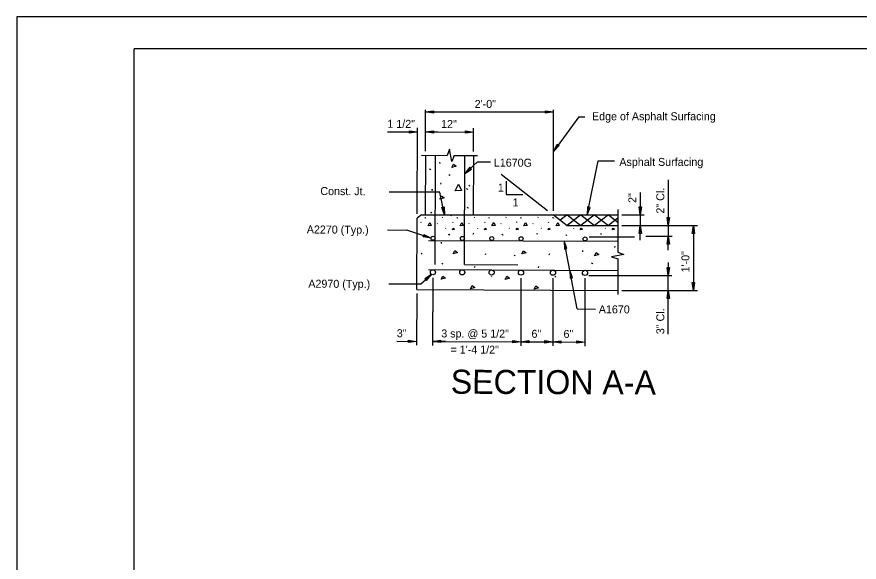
# Model space of a CAD drawing. Extents: x 2799.7 to 2896, y 515.2 to 573.9.
# Drawn here: x 2799.69 to 2834.77, y 551.18 to 573.89 of the extents above; entities that cross this region are included whole.
import ezdxf

# ---------------------------------------------------------------- set-up
doc = ezdxf.new("R2010")
doc.units = 0
for name, color, linetype in [('BR_AUTO DIMENSION', 7, 'Continuous'), ('BR_BORDER LINES', 7, 'Continuous'), ('BR_CONCRETE', 7, 'Continuous'), ('BR_DETAILS', 7, 'Continuous'), ('BR_REBAR', 7, 'Continuous'), ('BR_TABLE LINES', 7, 'Continuous'), ('BR_TEXT', 7, 'Continuous'), ('Level 31', 7, 'Continuous')]:
    doc.layers.add(name, color=color, linetype=linetype)

msp = doc.modelspace()

# ---------------------------------------------------------------- linework, layer by layer
at = {"layer": 'BR_AUTO DIMENSION'}
for p, q in [((2816.709, 568.294), (2816.709, 570.014)), ((2816.709, 569.93), (2822.042, 569.93)), ((2822.042, 565.808), (2822.042, 570.014)), ((2823.098, 569.724), (2822.042, 568.287)), ((2823.098, 569.724), (2823.349, 569.724)), ((2815.124, 569.104), (2816.38, 569.099)), ((2816.366, 565.69), (2816.38, 569.265)), ((2816.71, 568.294), (2816.714, 569.264)), ((2816.71, 568.294), (2816.714, 569.264)), ((2817.246, 569.095), (2816.713, 569.097)), ((2816.713, 569.097), (2818.713, 569.089)), ((2818.71, 568.286), (2818.714, 569.256)), ((2818.872, 567.855), (2818.354, 567.36)), ((2818.872, 567.855), (2819.425, 567.853)), ((2823.449, 565.641), (2823.908, 567.901)), ((2823.908, 567.901), (2824.59, 567.901)), ((2819.864, 567.336), (2821.798, 565.832)), ((2820.074, 567.05), (2820.074, 566.489)), ((2826.826, 567.108), (2826.826, 565.197)), ((2817.315, 566.584), (2815.196, 566.593)), ((2817.502, 565.641), (2817.315, 566.584)), ((2825.659, 566.578), (2825.659, 565.641)), ((2820.074, 566.489), (2820.772, 566.489)), ((2824.887, 565.641), (2825.826, 565.641)), ((2825.659, 565.641), (2825.659, 565.197)), ((2824.887, 565.197), (2825.826, 565.197)), ((2824.887, 565.197), (2828.037, 565.197)), ((2824.887, 565.197), (2826.992, 565.197)), ((2825.659, 564.595), (2825.659, 565.197)), ((2826.826, 565.197), (2826.826, 564.752)), ((2827.87, 565.197), (2827.87, 562.496)), ((2815.126, 565.016), (2815.941, 565.013)), ((2816.937, 564.671), (2815.941, 565.013)), ((2823.036, 561.725), (2822.484, 564.56)), ((2823.525, 564.725), (2825.421, 564.725)), ((2825.895, 564.752), (2826.992, 564.752)), ((2826.062, 564.752), (2826.992, 564.752)), ((2826.826, 564.176), (2826.826, 564.752)), ((2826.826, 564.219), (2826.826, 564.752)), ((2826.826, 563.654), (2826.826, 563.121)), ((2816.499, 562.757), (2816.968, 563.161)), ((2823.519, 563.121), (2826.968, 563.121)), ((2826.826, 562.496), (2826.826, 563.121)), ((2816.499, 562.757), (2815.188, 562.763)), ((2817.022, 563.029), (2817.01, 560.209)), ((2817.021, 562.981), (2817.01, 560.209)), ((2820.688, 563.014), (2820.677, 560.194)), ((2820.688, 563.014), (2820.677, 560.194)), ((2822.021, 563.008), (2822.01, 560.189)), ((2822.021, 563.008), (2822.01, 560.189)), ((2823.355, 563.003), (2823.343, 560.183)), ((2816.352, 562.365), (2816.343, 560.212)), ((2824.886, 562.496), (2828.037, 562.496)), ((2826.826, 560.676), (2826.826, 562.496)), ((2826.826, 561.963), (2826.826, 562.496)), ((2823.036, 561.725), (2823.788, 561.722)), ((2815.517, 560.382), (2816.344, 560.378)), ((2817.011, 560.376), (2820.677, 560.361)), ((2817.544, 560.374), (2817.011, 560.376)), ((2820.677, 560.361), (2822.011, 560.355)), ((2822.011, 560.355), (2823.344, 560.35))]:
    msp.add_line(p, q, dxfattribs=at)
for points in [[(2817.042, 569.88), (2816.709, 569.93), (2817.042, 569.98)], [(2821.709, 569.98), (2822.042, 569.93), (2821.709, 569.88)], [(2816.047, 569.15), (2816.38, 569.099), (2816.046, 569.05)], [(2817.046, 569.046), (2816.713, 569.097), (2817.047, 569.146)], [(2817.046, 569.046), (2816.713, 569.097), (2817.047, 569.146)], [(2818.38, 569.14), (2818.713, 569.089), (2818.379, 569.04)], [(2822.28, 568.526), (2822.042, 568.287), (2822.199, 568.585)], [(2818.561, 567.626), (2818.354, 567.36), (2818.63, 567.554)], [(2817.486, 565.978), (2817.502, 565.641), (2817.388, 565.958)], [(2823.466, 565.978), (2823.449, 565.641), (2823.564, 565.958)], [(2825.709, 565.975), (2825.659, 565.641), (2825.609, 565.975)], [(2826.876, 565.53), (2826.826, 565.197), (2826.776, 565.53)], [(2825.609, 564.863), (2825.659, 565.197), (2825.709, 564.863)], [(2825.609, 564.863), (2825.659, 565.197), (2825.709, 564.863)], [(2827.82, 564.863), (2827.87, 565.197), (2827.92, 564.863)], [(2816.643, 564.825), (2816.942, 564.67), (2816.61, 564.73)], [(2822.597, 564.242), (2822.484, 564.56), (2822.499, 564.223)], [(2826.776, 564.419), (2826.826, 564.752), (2826.876, 564.419)], [(2826.776, 564.419), (2826.826, 564.752), (2826.876, 564.419)], [(2826.876, 563.454), (2826.826, 563.121), (2826.776, 563.454)], [(2816.748, 562.906), (2816.968, 563.161), (2816.683, 562.982)], [(2822.835, 563.021), (2822.722, 563.339), (2822.736, 563.002)], [(2827.92, 562.83), (2827.87, 562.496), (2827.82, 562.83)], [(2826.776, 562.163), (2826.826, 562.496), (2826.876, 562.163)], [(2816.011, 560.43), (2816.344, 560.378), (2816.01, 560.33)], [(2817.344, 560.324), (2817.011, 560.376), (2817.344, 560.424)], [(2817.344, 560.324), (2817.011, 560.376), (2817.344, 560.424)], [(2820.344, 560.412), (2820.677, 560.361), (2820.344, 560.312)], [(2821.01, 560.309), (2820.677, 560.361), (2821.011, 560.409)], [(2821.677, 560.407), (2822.011, 560.355), (2821.677, 560.307)], [(2822.344, 560.304), (2822.011, 560.355), (2822.344, 560.404)], [(2823.011, 560.401), (2823.344, 560.35), (2823.01, 560.301)]]:
    msp.add_lwpolyline(points, close=True, dxfattribs=at)
at = {"layer": 'BR_BORDER LINES'}
for p in [(2894.359, 572.556), (2804.582, 516.556)]:
    msp.add_line(p, (2804.582, 572.556), dxfattribs=at)
at = {"layer": 'BR_CONCRETE'}
for p, q in [((2816.709, 568.127), (2816.699, 565.641)), ((2818.709, 568.119), (2818.699, 565.641)), ((2816.542, 565.641), (2816.365, 565.503)), ((2816.542, 565.641), (2822.042, 565.641)), ((2822.042, 565.641), (2822.614, 565.197)), ((2816.353, 562.532), (2816.365, 565.503)), ((2822.614, 565.197), (2824.72, 565.197)), ((2816.353, 562.532), (2824.72, 562.497))]:
    msp.add_line(p, q, dxfattribs=at)
at = {"layer": 'BR_DETAILS'}
for p, q in [((2816.542, 568.128), (2817.617, 568.123)), ((2817.906, 568.122), (2818.876, 568.118)), ((2817.301, 567.838), (2817.307, 567.788)), ((2816.883, 567.563), (2816.905, 567.53)), ((2816.906, 567.55), (2816.928, 567.517)), ((2817.678, 567.332), (2817.7, 567.299)), ((2817.7, 567.32), (2817.722, 567.286)), ((2817.349, 566.922), (2817.371, 566.972)), ((2816.956, 566.71), (2816.978, 566.677)), ((2816.978, 566.697), (2817, 566.664)), ((2818.42, 566.742), (2818.442, 566.708)), ((2818.442, 566.729), (2818.464, 566.696)), ((2818.537, 566.836), (2818.56, 566.886)), ((2818.449, 565.965), (2818.471, 565.931)), ((2818.471, 565.952), (2818.493, 565.919)), ((2824.72, 565.874), (2824.72, 564.096)), ((2816.688, 565.534), (2816.699, 565.518)), ((2816.699, 565.528), (2816.71, 565.511)), ((2816.914, 565.763), (2816.936, 565.729)), ((2816.936, 565.75), (2816.958, 565.717)), ((2817.42, 565.534), (2817.431, 565.559)), ((2817.787, 565.611), (2817.81, 565.661)), ((2818.017, 565.534), (2818.028, 565.518)), ((2818.028, 565.528), (2818.039, 565.511)), ((2818.75, 565.534), (2818.761, 565.559)), ((2819.346, 565.534), (2819.357, 565.518)), ((2819.357, 565.528), (2819.369, 565.511)), ((2820.079, 565.534), (2820.09, 565.559)), ((2820.676, 565.534), (2820.687, 565.518)), ((2820.687, 565.528), (2820.698, 565.511)), ((2821.408, 565.534), (2821.419, 565.559)), ((2822.005, 565.534), (2822.016, 565.518)), ((2822.015, 565.534), (2822.026, 565.518)), ((2822.026, 565.528), (2822.037, 565.511)), ((2816.524, 565.329), (2816.535, 565.354)), ((2817.196, 565.265), (2817.207, 565.29)), ((2817.853, 565.329), (2817.864, 565.354)), ((2818.525, 565.265), (2818.536, 565.29)), ((2819.183, 565.329), (2819.194, 565.354)), ((2819.854, 565.265), (2819.865, 565.29)), ((2820.512, 565.329), (2820.523, 565.354)), ((2821.183, 565.265), (2821.195, 565.29)), ((2821.841, 565.329), (2821.852, 565.354)), ((2817.542, 565.087), (2817.554, 565.071)), ((2817.668, 564.85), (2817.69, 564.817)), ((2817.69, 564.837), (2817.712, 564.804)), ((2818.702, 564.846), (2818.725, 564.896)), ((2818.872, 565.087), (2818.883, 565.071)), ((2819.896, 564.841), (2819.918, 564.808)), ((2819.918, 564.828), (2819.94, 564.795)), ((2820.201, 565.087), (2820.212, 565.071)), ((2821.361, 564.835), (2821.383, 564.885)), ((2821.53, 565.087), (2821.541, 565.071)), ((2822.554, 564.83), (2822.576, 564.797)), ((2822.576, 564.817), (2822.598, 564.784)), ((2822.87, 565.087), (2822.881, 565.071)), ((2824.019, 564.824), (2824.042, 564.874)), ((2824.199, 565.087), (2824.21, 565.071)), ((2817.363, 564.503), (2817.369, 564.453)), ((2823.252, 564.157), (2823.257, 564.107)), ((2824.592, 564.291), (2824.614, 564.341)), ((2816.547, 564.002), (2816.569, 564.052)), ((2819.205, 563.991), (2819.228, 564.041)), ((2820.399, 563.986), (2820.421, 563.953)), ((2820.421, 563.973), (2820.443, 563.94)), ((2821.864, 563.98), (2821.886, 564.03)), ((2824.72, 563.807), (2824.72, 562.324)), ((2817.411, 563.587), (2817.433, 563.637)), ((2818.754, 563.454), (2818.776, 563.504)), ((2821.412, 563.443), (2821.435, 563.493)), ((2823.629, 563.651), (2823.651, 563.617)), ((2823.651, 563.638), (2823.673, 563.605)), ((2819.446, 563.096), (2819.468, 563.062)), ((2822.104, 563.085), (2822.126, 563.052))]:
    msp.add_line(p, q, dxfattribs=at)
for points in [[(2817.906, 568.122), (2817.809, 567.865), (2817.714, 568.38), (2817.617, 568.123)], [(2817.807, 567.62), (2817.874, 567.759), (2817.985, 567.675), (2817.807, 567.62)], [(2817.942, 566.642), (2818.093, 566.925), (2818.208, 566.663), (2817.947, 566.642)], [(2817.307, 566.295), (2817.374, 566.434), (2817.485, 566.35), (2817.307, 566.295)], [(2816.821, 565.19), (2816.896, 565.332), (2816.954, 565.201), (2816.824, 565.19)], [(2818.15, 565.19), (2818.225, 565.332), (2818.283, 565.201), (2818.153, 565.19)], [(2819.48, 565.19), (2819.554, 565.332), (2819.613, 565.201), (2819.482, 565.19)], [(2820.809, 565.19), (2820.884, 565.332), (2820.942, 565.201), (2820.812, 565.19)], [(2822.148, 565.19), (2822.223, 565.332), (2822.282, 565.201), (2822.151, 565.19)], [(2817.834, 565.015), (2817.867, 565.085), (2817.923, 565.043), (2817.834, 565.015)], [(2819.163, 565.015), (2819.196, 565.085), (2819.252, 565.043), (2819.163, 565.015)], [(2820.492, 565.015), (2820.526, 565.085), (2820.581, 565.043), (2820.492, 565.015)], [(2821.822, 565.015), (2821.855, 565.085), (2821.911, 565.043), (2821.822, 565.015)], [(2823.161, 565.015), (2823.195, 565.085), (2823.25, 565.043), (2823.161, 565.015)], [(2824.491, 565.015), (2824.524, 565.085), (2824.579, 565.043), (2824.491, 565.015)], [(2817.868, 564.023), (2817.935, 564.161), (2818.046, 564.077), (2817.868, 564.023)], [(2820.727, 564.015), (2820.794, 564.153), (2820.905, 564.07), (2820.727, 564.015)], [(2823.758, 563.939), (2823.825, 564.077), (2823.936, 563.994), (2823.758, 563.939)], [(2824.72, 564.096), (2824.977, 564), (2824.463, 563.903), (2824.72, 563.807)], [(2817.369, 562.96), (2817.437, 563.098), (2817.547, 563.015), (2817.369, 562.96)], [(2820.028, 562.949), (2820.095, 563.088), (2820.206, 563.004), (2820.028, 562.949)], [(2818.584, 562.558), (2818.652, 562.697), (2818.762, 562.613), (2818.584, 562.558)], [(2821.243, 562.547), (2821.31, 562.686), (2821.421, 562.602), (2821.243, 562.547)]]:
    msp.add_lwpolyline(points, dxfattribs=at)
at = {"layer": 'BR_REBAR'}
for p, q in [((2817.116, 563.583), (2817.135, 568.125)), ((2818.339, 563.578), (2818.357, 568.12)), ((2816.839, 564.583), (2824.72, 564.551)), ((2818.339, 563.578), (2820.561, 563.569)), ((2816.834, 563.363), (2824.72, 563.331))]:
    msp.add_line(p, q, dxfattribs=at)
for centre, radius in [((2817.028, 564.668), 0.0833), ((2818.25, 564.663), 0.0833), ((2819.473, 564.658), 0.0833), ((2820.695, 564.653), 0.0833), ((2823.362, 564.642), 0.0833), ((2817.022, 563.255), 0.107), ((2818.245, 563.25), 0.107), ((2819.467, 563.245), 0.107), ((2820.689, 563.24), 0.107), ((2822.022, 563.234), 0.107), ((2823.356, 563.229), 0.107)]:
    msp.add_circle(centre, radius, dxfattribs=at)
at = {"layer": 'BR_TABLE LINES'}
for p, q in [((2822.047, 565.641), (2824.72, 565.641)), ((2822.614, 565.641), (2822.328, 565.419)), ((2822.614, 565.641), (2823.185, 565.197)), ((2823.185, 565.641), (2822.614, 565.197)), ((2823.757, 565.641), (2823.185, 565.197)), ((2823.185, 565.641), (2823.757, 565.197)), ((2823.757, 565.641), (2824.328, 565.197)), ((2824.328, 565.641), (2823.757, 565.197)), ((2824.328, 565.641), (2824.72, 565.337)), ((2824.72, 565.502), (2824.328, 565.197))]:
    msp.add_line(p, q, dxfattribs=at)
at = {"layer": 'Level 31'}
msp.add_lwpolyline([(2799.693, 515.223), (2895.694, 515.223), (2895.694, 573.89), (2799.693, 573.89)], close=True, dxfattribs=at)

# ---------------------------------------------------------------- texts
at = {"layer": 'BR_AUTO DIMENSION'}
for s, height, rotation, p in [('2\'-0"', 0.3333, 0, (2818.76, 570.097)), ('1 1/2"', 0.3333, 359.7654, (2815.125, 569.27)), ('12"', 0.3333, 359.7654, (2817.363, 569.261)), ('2" Cl.', 0.3333, 90, (2826.659, 565.697)), ('2"', 0.3333, 90, (2825.493, 566.141)), ('1\'-0"', 0.3333, 90, (2827.704, 563.248)), ('3" Cl.', 0.3333, 90, (2826.659, 560.676)), ('3"', 0.3333, 359.7654, (2815.517, 560.549)), ('3 sp. @ 5 1/2"', 0.33333, 359.7654, (2817.369, 560.541)), ('6"', 0.3333, 359.7654, (2821.126, 560.526)), ('6"', 0.3333, 359.7654, (2822.46, 560.52)), (' = 1\'-4 1/2"', 0.3333, 359.7654, (2817.63, 559.873))]:
    msp.add_text(s, height=height, rotation=rotation, dxfattribs=at).set_placement(p)
at = {"layer": 'BR_TEXT'}
for s, height, rotation, p in [('Edge of Asphalt Surfacing', 0.3333, 0, (2823.647, 569.583)), ('L1670G', 0.3333, 359.7654, (2819.559, 567.654)), ('Asphalt Surfacing', 0.3333, 0, (2824.787, 567.683)), ('1', 0.333, 0, (2819.725, 566.611)), ('Const. Jt.', 0.3333, 359.7654, (2812.332, 566.47)), ('1', 0.333, 0, (2820.341, 565.995)), ('A2270 (Typ.)', 0.3333, 359.7654, (2811.768, 564.87)), ('A2970 (Typ.)', 0.3333, 359.7654, (2811.832, 562.612)), ('A1670', 0.3333, 359.7654, (2823.929, 561.545)), ('SECTION A-A', 1, 359.7654, (2817.763, 558.197))]:
    msp.add_text(s, height=height, rotation=rotation, dxfattribs=at).set_placement(p)

doc.saveas('drawing.dxf')
